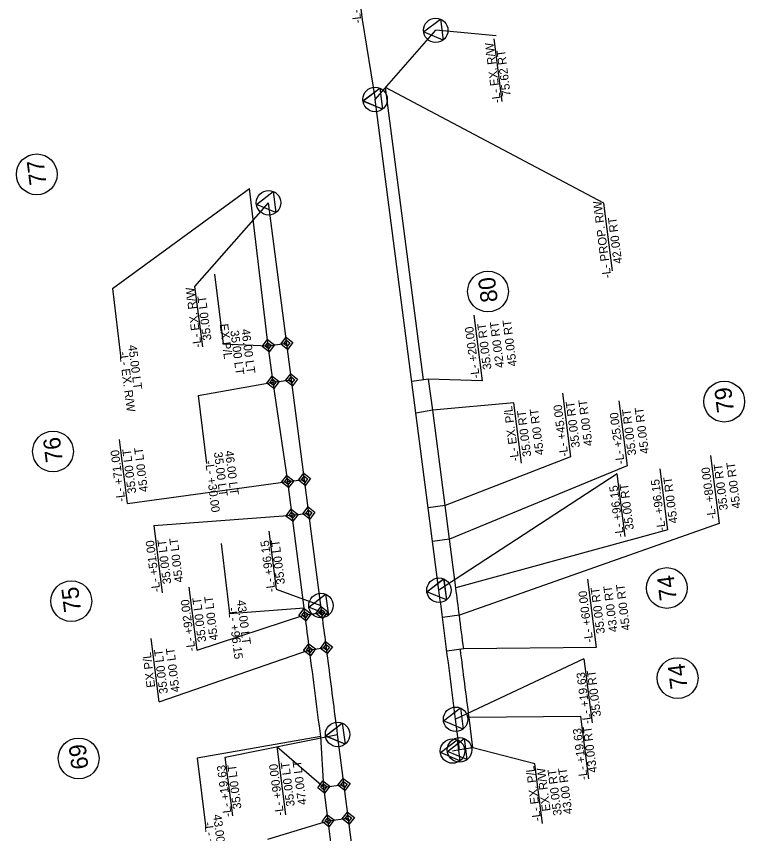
# Model space of a CAD drawing. Extents: x 2368169 to 2369183, y 801414 to 808542.
# Drawn here: x 2368213.4 to 2368641.8, y 807461.2 to 807941.9 of the extents above; entities that cross this region are included whole.
import ezdxf

# ---------------------------------------------------------------- set-up
doc = ezdxf.new("R2010")
doc.units = 0
for name, color, linetype in [('Prop Easement Construction', 7, 'Continuous'), ('Prop Easement Construction Station Offsets', 7, 'Continuous'), ('Prop Easement Permanent Drainage', 7, 'Continuous'), ('Prop Easement Permanent Drainage Station Offsets', 7, 'Continuous'), ('Prop Easement Permanent Drainage Utility', 7, 'Continuous'), ('Prop Easement Permanent Drainage Utility Station Offsets', 7, 'Continuous'), ('Prop Parcel Number CELL', 7, 'Continuous'), ('Prop Parcel Number Text', 7, 'Continuous'), ('Prop ROW Marker CELL', 7, 'Continuous'), ('Prop ROW Permanent Easement CELL', 7, 'Continuous'), ('Prop ROW RW Lines', 7, 'Continuous'), ('Prop ROW Station Offsets', 7, 'Continuous')]:
    doc.layers.add(name, color=color, linetype=linetype)

msp = doc.modelspace()

# ---------------------------------------------------------------- linework, layer by layer
at = {"layer": 'Prop Easement Construction'}
for p, q in [((2368452.93, 807728.12), (2368430.55, 807900.02)), ((2368361.58, 807748.17), (2368350.54, 807840.66)), ((2368372.99, 807668.3), (2368364.38, 807726.68)), ((2368465.59, 807654.14), (2368458.29, 807710.19)), ((2368382.65, 807594.08), (2368375.57, 807648.47)), ((2368471.9, 807605.7), (2368468.17, 807634.31)), ((2368482, 807511.75), (2368479.73, 807529.47)), ((2368394.23, 807488.63), (2368392.44, 807518.28)), ((2368482, 807511.75), (2368474.1, 807510.47)), ((2368405.17, 807403.33), (2368396.77, 807468.79))]:
    msp.add_line(p, q, dxfattribs=at)
for centre, radius, start, end in [((2328762.05, 802435.58), 40045, 7.394905, 7.418036), ((2328762.05, 802435.58), 39955, 7.412093, 7.418036), ((2328766.2, 802436.11), 39950.82, 7.308441, 7.382281), ((2328762.05, 802435.58), 40043, 7.308437, 7.366257)]:
    msp.add_arc(centre, radius, start, end, dxfattribs=at)
at = {"layer": 'Prop Easement Construction Station Offsets'}
for p, q in [((2368269.89, 807781.78), (2368350.54, 807840.66)), ((2368269.89, 807781.78), (2368274.89, 807740.68)), ((2368596.61, 807639.81), (2368592.02, 807675.72)), ((2368596.61, 807639.81), (2368471.9, 807605.7)), ((2368333.83, 807631.8), (2368338.83, 807590.7)), ((2368338.83, 807590.7), (2368382.65, 807594.08)), ((2368392.44, 807518.28), (2368319.84, 807505.63)), ((2368319.84, 807505.63), (2368324.84, 807464.53))]:
    msp.add_line(p, q, dxfattribs=at)
for points in [[(2368564.05, 807792.29), (2368558.98, 807832.05), (2368430.55, 807900.02)], [(2368550.13, 807493.5), (2368545.45, 807530.12), (2368479.73, 807529.47)]]:
    msp.add_lwpolyline(points, dxfattribs=at)
at = {"layer": 'Prop Easement Permanent Drainage'}
for p, q in [((2368455.91, 807728.51), (2368445.99, 807727.22)), ((2368458.29, 807710.19), (2368455.91, 807728.51)), ((2368458.29, 807710.19), (2368448.42, 807708.57)), ((2368465.59, 807654.14), (2368455.67, 807652.85)), ((2368468.17, 807634.31), (2368465.59, 807654.14)), ((2368468.17, 807634.31), (2368458.25, 807633.01)), ((2368473.98, 807589.66), (2368464.06, 807588.38)), ((2368476.55, 807569.81), (2368466.63, 807568.52))]:
    msp.add_line(p, q, dxfattribs=at)
msp.add_arc((2328762.05, 802435.58), 40045, 7.366257, 7.394905, dxfattribs=at)
at = {"layer": 'Prop Easement Permanent Drainage Station Offsets'}
for p, q in [((2368567.73, 807715.76), (2368572.61, 807677.5)), ((2368621.63, 807683.52), (2368626.73, 807643.58)), ((2368572.61, 807677.5), (2368468.17, 807634.31)), ((2368626.73, 807643.58), (2368473.98, 807589.66)), ((2368549.28, 807610.87), (2368554.41, 807570.74)), ((2368554.41, 807570.74), (2368476.55, 807569.81))]:
    msp.add_line(p, q, dxfattribs=at)
for points in [[(2368482.54, 807766.23), (2368487.47, 807727.6), (2368455.91, 807728.51)], [(2368534.6, 807720.29), (2368539.4, 807682.73), (2368465.59, 807654.14)], [(2368510.54, 807679.1), (2368506.01, 807714.52), (2368458.29, 807710.19)]]:
    msp.add_lwpolyline(points, dxfattribs=at)
at = {"layer": 'Prop Easement Permanent Drainage Utility'}
for p, q in [((2368361.58, 807748.17), (2368372.48, 807749.6)), ((2368364.38, 807726.68), (2368361.58, 807748.17)), ((2368364.38, 807726.68), (2368375.28, 807728.1)), ((2368372.99, 807668.3), (2368382.9, 807669.59)), ((2368375.57, 807648.47), (2368372.99, 807668.3)), ((2368375.57, 807648.47), (2368385.48, 807649.76)), ((2368383.18, 807589.97), (2368393.1, 807591.26)), ((2368385.86, 807569.35), (2368395.78, 807570.65)), ((2368394.23, 807488.63), (2368406.13, 807490.16)), ((2368396.77, 807468.79), (2368394.23, 807488.63)), ((2368396.77, 807468.79), (2368408.68, 807470.32))]:
    msp.add_line(p, q, dxfattribs=at)
msp.add_arc((2328762.05, 802435.58), 39955, 7.382277, 7.412093, dxfattribs=at)
at = {"layer": 'Prop Easement Permanent Drainage Utility Station Offsets'}
for p, q in [((2368329.96, 807790.33), (2368334.95, 807749.23)), ((2368334.95, 807749.23), (2368361.58, 807748.17)), ((2368320.36, 807718.87), (2368364.38, 807726.68)), ((2368320.36, 807718.87), (2368325.33, 807678.98)), ((2368278.69, 807655.41), (2368273.99, 807693.1)), ((2368278.69, 807655.41), (2368372.99, 807668.3)), ((2368294.22, 807642.4), (2368375.57, 807648.47)), ((2368294.22, 807642.4), (2368299.15, 807602.85)), ((2368319.77, 807569.1), (2368315.13, 807606.27)), ((2368319.77, 807569.1), (2368383.18, 807589.97)), ((2368297.33, 807538.66), (2368292.67, 807576.04)), ((2368297.33, 807538.66), (2368385.86, 807569.35)), ((2368366.53, 807512.42), (2368371.67, 807472.21)), ((2368366.53, 807512.42), (2368394.23, 807488.63)), ((2368361.38, 807457.88), (2368396.77, 807468.79))]:
    msp.add_line(p, q, dxfattribs=at)
at = {"layer": 'Prop Parcel Number CELL'}
for p, q in [((2368225.39, 807848.96), (2368225.39, 807848.96)), ((2368490.83, 807780.06), (2368490.83, 807780.06)), ((2368629.81, 807715.31), (2368629.81, 807715.31)), ((2368234.95, 807685.98), (2368234.95, 807685.98)), ((2368596.01, 807605.68), (2368596.01, 807605.68)), ((2368245.7, 807597.95), (2368245.7, 807597.95)), ((2368602.38, 807552.69), (2368602.38, 807552.69)), ((2368250.05, 807505.45), (2368250.05, 807505.45))]:
    msp.add_line(p, q, dxfattribs=at)
for centre in [(2368225.39, 807848.96), (2368490.83, 807780.06), (2368629.81, 807715.31), (2368234.95, 807685.98), (2368596.01, 807605.68), (2368245.7, 807597.95), (2368602.38, 807552.69), (2368250.05, 807505.45)]:
    msp.add_circle(centre, 12, dxfattribs=at)
at = {"layer": 'Prop ROW Marker CELL'}
for p, q in [((2368460.07, 807933.67), (2368460.07, 807933.67)), ((2368460.07, 807933.67), (2368460.07, 807933.67)), ((2368424.4, 807893.02), (2368424.4, 807893.02)), ((2368424.4, 807893.02), (2368424.4, 807893.02)), ((2368361.73, 807832.24), (2368361.73, 807832.24)), ((2368361.73, 807832.24), (2368361.73, 807832.24)), ((2368461.98, 807604.4), (2368461.98, 807604.4)), ((2368461.98, 807604.4), (2368461.98, 807604.4)), ((2368392.57, 807595.37), (2368392.57, 807595.37)), ((2368392.57, 807595.37), (2368392.57, 807595.37)), ((2368471.79, 807528.45), (2368471.79, 807528.45)), ((2368471.79, 807528.45), (2368471.79, 807528.45)), ((2368402.36, 807519.55), (2368402.36, 807519.55)), ((2368402.36, 807519.55), (2368402.36, 807519.55)), ((2368469.97, 807509.8), (2368469.97, 807509.8)), ((2368469.97, 807509.8), (2368469.97, 807509.8)), ((2368474.1, 807510.47), (2368474.1, 807510.47)), ((2368474.1, 807510.47), (2368474.1, 807510.47))]:
    msp.add_line(p, q, dxfattribs=at)
for points in [[(2368464.44, 807927.93), (2368452.93, 807932.75), (2368462.84, 807940.33)], [(2368464.43, 807927.93), (2368452.93, 807932.76), (2368462.85, 807940.33)], [(2368428.77, 807887.28), (2368417.26, 807892.1), (2368427.17, 807899.68)], [(2368428.77, 807887.27), (2368417.26, 807892.11), (2368427.18, 807899.67)], [(2368366.09, 807826.5), (2368354.58, 807831.32), (2368364.5, 807838.9)], [(2368366.09, 807826.49), (2368354.58, 807831.32), (2368364.5, 807838.89)], [(2368466.35, 807598.67), (2368454.84, 807603.48), (2368464.75, 807611.06)], [(2368466.34, 807598.66), (2368454.84, 807603.49), (2368464.76, 807611.06)], [(2368396.93, 807589.63), (2368385.42, 807594.45), (2368395.34, 807602.03)], [(2368396.93, 807589.62), (2368385.42, 807594.45), (2368395.34, 807602.02)], [(2368476.16, 807522.72), (2368464.65, 807527.53), (2368474.57, 807535.11)], [(2368476.16, 807522.71), (2368464.65, 807527.54), (2368474.57, 807535.11)], [(2368406.73, 807513.81), (2368395.22, 807518.63), (2368405.13, 807526.21)], [(2368406.73, 807513.81), (2368395.22, 807518.64), (2368405.14, 807526.21)], [(2368474.34, 807504.06), (2368462.83, 807508.88), (2368472.74, 807516.46)], [(2368474.33, 807504.06), (2368462.83, 807508.89), (2368472.75, 807516.46)], [(2368478.47, 807504.73), (2368466.96, 807509.55), (2368476.87, 807517.13)], [(2368478.46, 807504.73), (2368466.96, 807509.56), (2368476.88, 807517.13)]]:
    msp.add_lwpolyline(points, close=True, dxfattribs=at)
for centre in [(2368460.07, 807933.67), (2368424.4, 807893.02), (2368361.73, 807832.24), (2368461.98, 807604.4), (2368392.57, 807595.37), (2368471.79, 807528.45), (2368402.36, 807519.55), (2368469.97, 807509.8), (2368474.1, 807510.47)]:
    msp.add_circle(centre, 7.2, dxfattribs=at)
at = {"layer": 'Prop ROW Permanent Easement CELL'}
for p, q in [((2368372.48, 807749.6), (2368372.48, 807749.6)), ((2368361.58, 807748.17), (2368361.58, 807748.17)), ((2368364.38, 807726.68), (2368364.38, 807726.68)), ((2368375.28, 807728.1), (2368375.28, 807728.1)), ((2368372.99, 807668.3), (2368372.99, 807668.3)), ((2368382.9, 807669.59), (2368382.9, 807669.59)), ((2368375.57, 807648.47), (2368375.57, 807648.47)), ((2368385.48, 807649.76), (2368385.48, 807649.76)), ((2368393.1, 807591.26), (2368393.1, 807591.26)), ((2368383.18, 807589.97), (2368383.18, 807589.97)), ((2368385.86, 807569.35), (2368385.86, 807569.35)), ((2368395.78, 807570.65), (2368395.78, 807570.65)), ((2368406.13, 807490.16), (2368406.13, 807490.16)), ((2368394.23, 807488.63), (2368394.23, 807488.63)), ((2368396.77, 807468.79), (2368396.77, 807468.79)), ((2368408.68, 807470.32), (2368408.68, 807470.32))]:
    msp.add_line(p, q, dxfattribs=at)
for points in [[(2368362.05, 807744.6), (2368358.01, 807747.7), (2368361.11, 807751.74), (2368365.15, 807748.64)], [(2368361.81, 807746.39), (2368359.79, 807747.94), (2368361.34, 807749.96), (2368363.36, 807748.41)], [(2368372.96, 807746.04), (2368368.92, 807749.13), (2368372.01, 807753.17), (2368376.05, 807750.08)], [(2368372.72, 807747.82), (2368370.7, 807749.37), (2368372.25, 807751.39), (2368374.27, 807749.84)], [(2368364.85, 807723.11), (2368360.81, 807726.21), (2368363.9, 807730.25), (2368367.94, 807727.15)], [(2368375.76, 807724.53), (2368371.72, 807727.63), (2368374.81, 807731.67), (2368378.85, 807728.57)], [(2368364.61, 807724.89), (2368362.59, 807726.44), (2368364.14, 807728.46), (2368366.16, 807726.91)], [(2368375.52, 807726.31), (2368373.5, 807727.86), (2368375.05, 807729.88), (2368377.07, 807728.33)], [(2368383.37, 807666.02), (2368379.33, 807669.12), (2368382.43, 807673.16), (2368386.47, 807670.06)], [(2368373.46, 807664.73), (2368369.42, 807667.83), (2368372.51, 807671.87), (2368376.55, 807668.77)], [(2368373.22, 807666.52), (2368371.2, 807668.06), (2368372.75, 807670.08), (2368374.77, 807668.54)], [(2368383.14, 807667.81), (2368381.12, 807669.36), (2368382.67, 807671.38), (2368384.69, 807669.83)], [(2368385.96, 807646.19), (2368381.91, 807649.29), (2368385.01, 807653.33), (2368389.05, 807650.23)], [(2368376.04, 807644.9), (2368372, 807648), (2368375.09, 807652.04), (2368379.14, 807648.94)], [(2368375.8, 807646.68), (2368373.78, 807648.23), (2368375.33, 807650.25), (2368377.35, 807648.7)], [(2368385.72, 807647.97), (2368383.7, 807649.52), (2368385.25, 807651.54), (2368387.27, 807650)], [(2368383.66, 807586.4), (2368379.61, 807589.49), (2368382.71, 807593.53), (2368386.75, 807590.44)], [(2368383.42, 807588.18), (2368381.4, 807589.73), (2368382.95, 807591.75), (2368384.97, 807590.2)], [(2368393.57, 807587.69), (2368389.53, 807590.78), (2368392.63, 807594.82), (2368396.67, 807591.73)], [(2368393.34, 807589.47), (2368391.32, 807591.02), (2368392.86, 807593.04), (2368394.88, 807591.49)], [(2368386.33, 807565.78), (2368382.29, 807568.88), (2368385.39, 807572.92), (2368389.43, 807569.82)], [(2368396.25, 807567.08), (2368392.21, 807570.18), (2368395.3, 807574.22), (2368399.34, 807571.12)], [(2368396.01, 807568.87), (2368393.99, 807570.41), (2368395.54, 807572.43), (2368397.56, 807570.89)], [(2368386.1, 807567.56), (2368384.08, 807569.11), (2368385.62, 807571.13), (2368387.65, 807569.58)], [(2368394.7, 807485.06), (2368390.66, 807488.16), (2368393.76, 807492.2), (2368397.8, 807489.1)], [(2368394.47, 807486.85), (2368392.45, 807488.39), (2368393.99, 807490.41), (2368396.01, 807488.87)], [(2368406.61, 807486.59), (2368402.56, 807489.68), (2368405.66, 807493.72), (2368409.7, 807490.63)], [(2368406.37, 807488.37), (2368404.35, 807489.92), (2368405.9, 807491.94), (2368407.92, 807490.39)], [(2368397.25, 807465.22), (2368393.21, 807468.32), (2368396.3, 807472.36), (2368400.34, 807469.27)], [(2368409.15, 807466.75), (2368405.11, 807469.85), (2368408.2, 807473.89), (2368412.25, 807470.79)], [(2368408.91, 807468.53), (2368406.89, 807470.08), (2368408.44, 807472.1), (2368410.46, 807470.56)], [(2368397.01, 807467.01), (2368394.99, 807468.56), (2368396.54, 807470.58), (2368398.56, 807469.03)]]:
    msp.add_lwpolyline(points, close=True, dxfattribs=at)
at = {"layer": 'Prop ROW RW Lines'}
for p, q in [((2368424.4, 807893.02), (2368460.07, 807933.67)), ((2368461.98, 807604.4), (2368424.4, 807893.02)), ((2368392.57, 807595.37), (2368361.73, 807832.24)), ((2368474.1, 807510.47), (2368471.79, 807528.45)), ((2368481.04, 806906.1), (2368402.36, 807519.55)), ((2368474.1, 807510.47), (2368469.97, 807509.8))]:
    msp.add_line(p, q, dxfattribs=at)
for radius, start, end in [(40035, 7.308437, 7.418036), (39965, 7.370696, 7.418036), (39965, 7.308437, 7.370696)]:
    msp.add_arc((2328762.05, 802435.58), radius, start, end, dxfattribs=at)
at = {"layer": 'Prop ROW Station Offsets'}
for p, q in [((2368495.55, 807930.5), (2368460.07, 807933.67)), ((2368499.24, 807891.91), (2368494.54, 807928.67)), ((2368566.8, 807672.82), (2368461.98, 807604.4)), ((2368571.49, 807636.06), (2368566.8, 807672.82)), ((2368547.22, 807563.98), (2368471.79, 807528.45)), ((2368547.22, 807563.98), (2368552.03, 807526.37)), ((2368336.29, 807506.16), (2368402.36, 807519.55)), ((2368518.45, 807502.27), (2368482, 807511.75)), ((2368340.7, 807471.61), (2368336.29, 807506.16)), ((2368522.94, 807467.15), (2368518.45, 807502.27))]:
    msp.add_line(p, q, dxfattribs=at)
for points in [[(2368412.48, 807974.29), (2368416.84, 807940.11), (2368424.4, 807893.02)], [(2368323.02, 807747.43), (2368318.46, 807783.08), (2368361.73, 807832.24)], [(2368361.83, 807639.06), (2368366.17, 807605.06), (2368392.57, 807595.37)]]:
    msp.add_lwpolyline(points, dxfattribs=at)

# ---------------------------------------------------------------- texts
at = {"layer": 'Prop Easement Construction Station Offsets'}
for s, rotation, p in [('-L- PROP. R/W', 97.2784, (2368563.32, 807788.2)), ('42.00 RT', 97.2784, (2368569.79, 807796.74)), ('45.00 LT', 277.2784, (2368279.17, 807748.38)), ('-L- EX. R/W', 277.2784, (2368273.91, 807744.37)), ('-L- +96.15', 97.2784, (2368595.38, 807639.53)), ('45.00 RT', 97.2784, (2368602.37, 807643.99)), ('43.00 LT', 277.2784, (2368343.1, 807598.4)), ('-L- +96.15', 277.2784, (2368337.9, 807593.96)), ('43.00 RT', 97.2784, (2368555, 807497.34)), ('-L- +19.63', 97.2784, (2368549.49, 807493.08)), ('43.00 LT', 277.2784, (2368329.11, 807472.23)), ('-L- +19.63', 277.2784, (2368323.91, 807467.8))]:
    msp.add_text(s, height=5, rotation=rotation, dxfattribs=at).set_placement(p)
at = {"layer": 'Prop Easement Permanent Drainage Station Offsets'}
for s, p in [('-L- +20.00', (2368486, 807729.28)), ('35.00 RT', (2368492.9, 807734.44)), ('42.00 RT', (2368500.34, 807735.39)), ('45.00 RT', (2368507.78, 807736.34)), ('45.00 RT', (2368552.4, 807689.45)), ('-L- EX. P/L', (2368509.1, 807680.52)), ('-L- +45.00', (2368538.06, 807683.35)), ('35.00 RT', (2368544.96, 807688.5)), ('45.00 RT', (2368585.53, 807684.92)), ('35.00 RT', (2368516.32, 807683.17)), ('45.00 RT', (2368523.76, 807684.12)), ('-L- +25.00', (2368571.19, 807678.81)), ('35.00 RT', (2368578.09, 807683.97)), ('35.00 RT', (2368631.99, 807651.73)), ('45.00 RT', (2368639.43, 807652.68)), ('-L- +80.00', (2368625.08, 807646.57)), ('35.00 RT', (2368559.64, 807579.08)), ('43.00 RT', (2368567.08, 807580.03)), ('45.00 RT', (2368574.52, 807580.98)), ('-L- +60.00', (2368552.74, 807573.92))]:
    msp.add_text(s, height=5, rotation=97.2784, dxfattribs=at).set_placement(p)
at = {"layer": 'Prop Easement Permanent Drainage Utility Station Offsets'}
for s, rotation, p in [('EX P/L', 277.2784, (2368332.97, 807760.8)), ('35.00 LT', 277.2784, (2368339.23, 807756.93)), ('46.00 LT', 277.2784, (2368345.73, 807757.76)), ('35.00 LT', 97.1063, (2368283.92, 807661.52)), ('45.00 LT', 97.1063, (2368290.86, 807662.41)), ('-L- +71.00', 97.1063, (2368277.46, 807656.73)), ('35.00 LT', 277.1063, (2368329.59, 807685.46)), ('46.00 LT', 277.1063, (2368336.1, 807686.29)), ('-L- +30.00', 277.1063, (2368324.47, 807680.33)), ('45.00 LT', 97.1063, (2368311.53, 807609.18)), ('-L- +51.00', 97.1063, (2368298.13, 807603.54)), ('35.00 LT', 97.1063, (2368304.58, 807608.31)), ('45.00 LT', 97.1063, (2368332.07, 807575.04)), ('-L- +92.00', 97.1063, (2368318.74, 807568.8)), ('35.00 LT', 97.1063, (2368325.13, 807574.17)), ('EX P/L', 97.1063, (2368295.07, 807547.4)), ('35.00 LT', 97.1063, (2368302.57, 807543.76)), ('45.00 LT', 97.1063, (2368309.52, 807544.63)), ('-L- +90.00', 97.2784, (2368370.82, 807472.12)), ('35.00 LT', 97.2784, (2368377.19, 807477.51)), ('47.00 LT', 97.2784, (2368384.13, 807478.4))]:
    msp.add_text(s, height=5, rotation=rotation, dxfattribs=at).set_placement(p)
at = {"layer": 'Prop Parcel Number Text'}
for s, rotation, p in [('77', 97.1063, (2368231.21, 807843.16)), ('80', 97.1063, (2368496.65, 807774.27)), ('79', 97.1063, (2368635.63, 807709.53)), ('76', 97.1063, (2368240.77, 807680.17)), ('74', 97.1063, (2368601.89, 807598.92)), ('75', 97.1063, (2368251.53, 807592.1)), ('74', 97.2784, (2368608.22, 807546.9)), ('69', 97.2784, (2368255.89, 807499.65))]:
    msp.add_text(s, height=10, rotation=rotation, dxfattribs=at).set_placement(p)
at = {"layer": 'Prop ROW Station Offsets'}
for s, p in [('-L- +87.20', (2368416.47, 807938.08)), ('-L- EX. R/W', (2368498.47, 807891.3)), ('75.62 RT', (2368504.27, 807895.17)), ('-L- EX. R/W', (2368322.39, 807747.41)), ('35.00 LT', (2368328.16, 807751.59)), ('-L- +96.15', (2368570.89, 807635.86)), ('35.00 RT', (2368576.64, 807640.16)), ('-L- +96.15', (2368365.73, 807603.55)), ('35.00 LT', (2368371.44, 807608.15)), ('-L- +19.63', (2368551.61, 807526.02)), ('35.00 RT', (2368557.36, 807530.32)), ('-L- +19.63', (2368340.1, 807471.39)), ('35.00 LT', (2368345.81, 807475.98)), ('-L- EX. P/L', (2368522.09, 807468.86)), ('43.00 RT', (2368540.47, 807472.94)), ('EX. R/W', (2368527.65, 807474.66)), ('35.00 RT', (2368534.27, 807472.15))]:
    msp.add_text(s, height=5, rotation=97.2784, dxfattribs=at).set_placement(p)

doc.saveas('drawing.dxf')
